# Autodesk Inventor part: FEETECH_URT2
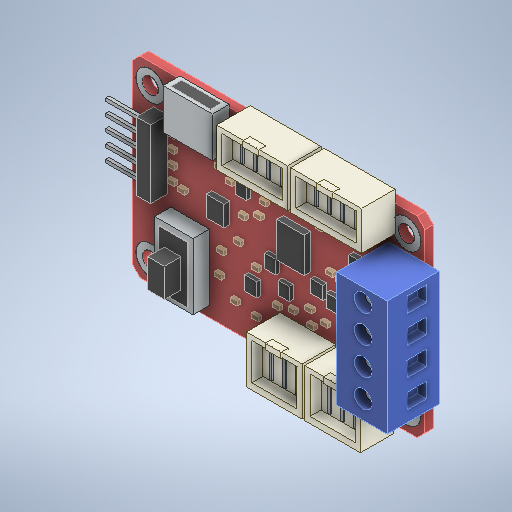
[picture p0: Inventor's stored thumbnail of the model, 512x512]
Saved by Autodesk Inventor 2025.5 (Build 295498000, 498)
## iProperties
Created: 2026-10
Part Number: FEETECH_URT2
Material: Genérico
Description: Open CASCADE Model
Document SubType Name: Modeling
Designer: Luis M
Authority: Unknown
Density: 1 g/cm^3
Appearance: Valor por defecto
Company: Open CASCADE
Title: Open CASCADE Shape Model
Author: Author
Sending System: Open CASCADE 7.9
Preprocessor: Open CASCADE STEP processor 7.9
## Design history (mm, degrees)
feature "PCB_55p8_x_36p6_4xD3_1:1"
feature "Mounting_hole_annuli_2:1"
feature "Mounting_hole_annuli_2:2"
feature "Mounting_hole_annuli_2:3"
feature "Mounting_hole_annuli_2:4"
feature "White_connector_housings_3:1"
feature "White_connector_housings_3:2"
feature "White_connector_housings_3:3"
feature "White_connector_housings_3:4"
feature "White_connector_housings_3:5"
feature "White_connector_housings_3:6"
feature "White_connector_housings_3:7"
feature "White_connector_housings_3:8"
feature "White_connector_contacts_4:1"
feature "White_connector_contacts_4:2"
feature "White_connector_contacts_4:3"
feature "White_connector_contacts_4:4"
feature "White_connector_contacts_4:5"
feature "White_connector_contacts_4:6"
feature "White_connector_contacts_4:7"
feature "White_connector_contacts_4:8"
feature "White_connector_contacts_4:9"
feature "White_connector_contacts_4:10"
feature "White_connector_contacts_4:11"
feature "White_connector_contacts_4:12"
feature "White_connector_contacts_4:13"
feature "White_connector_contacts_4:14"
feature "Four_way_terminal_block_5:1"
feature "Terminal_screw_heads_6:1"
feature "Terminal_screw_heads_6:2"
feature "Terminal_screw_heads_6:3"
feature "Terminal_screw_heads_6:4"
feature "USB_C_shell_7:1"
feature "USB_C_port_insert_8:1"
feature "USB_C_shell_tabs_9:1"
feature "USB_C_shell_tabs_9:2"
feature "UART_header_insulator_10:1"
feature "UART_header_5pins_2p54pitch_11:1"
feature "UART_header_5pins_2p54pitch_11:2"
feature "UART_header_5pins_2p54pitch_11:3"
feature "UART_header_5pins_2p54pitch_11:4"
feature "UART_header_5pins_2p54pitch_11:5"
feature "Slide_switch_housing_12:1"
feature "Slide_switch_track_13:1"
feature "Slide_switch_actuator_14:1"
feature "Integrated_circuits_and_SOT_packages_15:1"
feature "Integrated_circuits_and_SOT_packages_15:2"
feature "Integrated_circuits_and_SOT_packages_15:3"
feature "Integrated_circuits_and_SOT_packages_15:4"
feature "Integrated_circuits_and_SOT_packages_15:5"
feature "Integrated_circuits_and_SOT_packages_15:6"
feature "Integrated_circuits_and_SOT_packages_15:7"
feature "Integrated_circuits_and_SOT_packages_15:8"
feature "Integrated_circuits_and_SOT_packages_15:9"
feature "Integrated_circuits_and_SOT_packages_15:10"
feature "SMD_passives_approximate_16:1"
feature "SMD_passives_approximate_16:2"
feature "SMD_passives_approximate_16:3"
feature "SMD_passives_approximate_16:4"
feature "SMD_passives_approximate_16:5"
feature "SMD_passives_approximate_16:6"
feature "SMD_passives_approximate_16:7"
feature "SMD_passives_approximate_16:8"
feature "SMD_passives_approximate_16:9"
feature "SMD_passives_approximate_16:10"
feature "SMD_passives_approximate_16:11"
feature "SMD_passives_approximate_16:12"
feature "SMD_passives_approximate_16:13"
feature "SMD_passives_approximate_16:14"
feature "SMD_passives_approximate_16:15"
feature "SMD_passives_approximate_16:16"
feature "SMD_passives_approximate_16:17"
feature "SMD_passives_approximate_16:18"
feature "SMD_passives_approximate_16:19"
feature "SMD_passives_approximate_16:20"
feature "SMD_passives_approximate_16:21"
feature "SMD_passives_approximate_16:22"
feature "SMD_passives_approximate_16:23"
feature "SMD_passives_approximate_16:24"
feature "SMD_passives_approximate_16:25"
feature "SMD_passives_approximate_16:26"
feature "SMD_passives_approximate_16:27"
feature "SMD_passives_approximate_16:28"
feature "SMD_passives_approximate_16:29"
feature "SMD_passives_approximate_16:30"
feature "SMD_passives_approximate_16:31"
feature "SMD_passives_approximate_16:32"
feature "SMD_passives_approximate_16:33"
feature "SMD_passives_approximate_16:34"
feature "SMD_passives_approximate_16:35"
node "Sólido1"
node "Sólido2"
node "Sólido3"
node "Sólido4"
node "Sólido5"
node "Sólido6"
node "Sólido7"
node "Sólido8"
node "Sólido9"
node "Sólido10"
node "Sólido11"
node "Sólido12"
node "Sólido13"
node "Sólido14"
node "Sólido15"
node "Sólido16"
node "Sólido17"
node "Sólido18"
node "Sólido19"
node "Sólido20"
node "Sólido21"
node "Sólido22"
node "Sólido23"
node "Sólido24"
node "Sólido25"
node "Sólido26"
node "Sólido27"
node "Sólido28"
node "Sólido29"
node "Sólido30"
node "Sólido31"
node "Sólido32"
node "Sólido33"
node "Sólido34"
node "Sólido35"
node "Sólido36"
node "Sólido37"
node "Sólido38"
node "Sólido39"
node "Sólido40"
node "Sólido41"
node "Sólido42"
node "Sólido43"
node "Sólido44"
node "Sólido45"
node "Sólido46"
node "Sólido47"
node "Sólido48"
node "Sólido49"
node "Sólido50"
node "Sólido51"
node "Sólido52"
node "Sólido53"
node "Sólido54"
node "Sólido55"
node "Sólido56"
node "Sólido57"
node "Sólido58"
node "Sólido59"
node "Sólido60"
node "Sólido61"
node "Sólido62"
node "Sólido63"
node "Sólido64"
node "Sólido65"
node "Sólido66"
node "Sólido67"
node "Sólido68"
node "Sólido69"
node "Sólido70"
node "Sólido71"
node "Sólido72"
node "Sólido73"
node "Sólido74"
node "Sólido75"
node "Sólido76"
node "Sólido77"
node "Sólido78"
node "Sólido79"
node "Sólido80"
node "Sólido81"
node "Sólido82"
node "Sólido83"
node "Sólido84"
node "Sólido85"
node "Sólido86"
node "Sólido87"
node "Sólido88"
node "Sólido89"
node "Sólido90"
